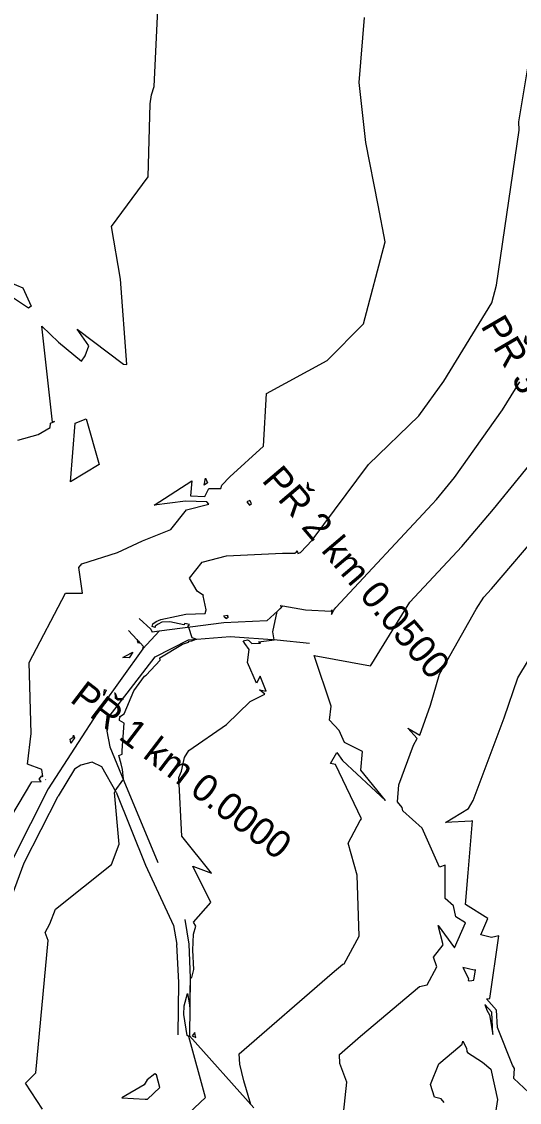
# Model space of a CAD drawing. Extents: x -549394 to -546608, y -1037055 to -1033629.
# Drawn here: x -547595.6 to -547431.1, y -1035265.1 to -1034908.3 of the extents above; entities that cross this region are included whole.
import ezdxf

# ---------------------------------------------------------------- set-up
doc = ezdxf.new("R2010")
doc.units = 0
for name, color, linetype in [('hlavni_vrst', 7, 'Continuous'), ('hrana_L', 7, 'Continuous'), ('norm_vrst', 7, 'Continuous'), ('x_popis_pricne_rezy_C14', 7, 'Continuous')]:
    doc.layers.add(name, color=color, linetype=linetype)

msp = doc.modelspace()

# ---------------------------------------------------------------- linework, layer by layer
at = {"layer": 'hlavni_vrst'}
for p, q in [((-547439.63, -1035069.29), (-547423.11, -1035049.09)), ((-547450.13, -1035081.66), (-547439.63, -1035069.29)), ((-547467.32, -1035100.01), (-547450.13, -1035081.66)), ((-547479.83, -1035120.29), (-547467.32, -1035100.01)), ((-547498.94, -1035117.55), (-547498.94, -1035117.55)), ((-547498.94, -1035117.55), (-547498.94, -1035117.55)), ((-547498.94, -1035117.55), (-547498.94, -1035117.55)), ((-547498.94, -1035117.55), (-547480.25, -1035121.02)), ((-547498.94, -1035117.55), (-547498.94, -1035117.55)), ((-547493.26, -1035134.32), (-547498.94, -1035117.55)), ((-547498.94, -1035117.55), (-547498.94, -1035117.55)), ((-547498.94, -1035117.55), (-547498.94, -1035117.55)), ((-547498.94, -1035117.55), (-547498.94, -1035117.55)), ((-547480.25, -1035121.02), (-547479.83, -1035120.29)), ((-547493.87, -1035138.92), (-547493.26, -1035134.32)), ((-547490.66, -1035142.33), (-547493.87, -1035138.92)), ((-547488.93, -1035146.33), (-547490.66, -1035142.33)), ((-547482.97, -1035149.28), (-547488.93, -1035146.33)), ((-547493.51, -1035153.28), (-547491.47, -1035149.64)), ((-547491.47, -1035149.64), (-547489.56, -1035152.3)), ((-547483.54, -1035155.44), (-547482.97, -1035149.28)), ((-547491.88, -1035153.58), (-547493.51, -1035153.28)), ((-547483.29, -1035171.5), (-547491.88, -1035153.58)), ((-547489.56, -1035152.3), (-547475.31, -1035165.43)), ((-547475.31, -1035165.43), (-547483.54, -1035155.44)), ((-547487.72, -1035179.56), (-547483.7, -1035172.06)), ((-547483.7, -1035172.06), (-547483.29, -1035171.5)), ((-547484.7, -1035190.12), (-547487.72, -1035179.56)), ((-547483.99, -1035210.2), (-547484.7, -1035190.12)), ((-547488.97, -1035219.38), (-547483.99, -1035210.2)), ((-547492.94, -1035222.45), (-547489.42, -1035219.48)), ((-547489.42, -1035219.48), (-547488.97, -1035219.38)), ((-547523.68, -1035249.07), (-547492.94, -1035222.45)), ((-547523.47, -1035252.45), (-547523.68, -1035249.07)), ((-547522.11, -1035257.98), (-547523.47, -1035252.45)), ((-547519.79, -1035265.79), (-547522.11, -1035257.98))]:
    msp.add_line(p, q, dxfattribs=at)
at = {"layer": 'hrana_L'}
for p, q in [((-547509.73, -1035101.72), (-547514.54, -1035106.1)), ((-547509.73, -1035101.72), (-547509.94, -1035101)), ((-547556.67, -1035105.35), (-547552.91, -1035108.87)), ((-547552.91, -1035108.87), (-547552.47, -1035109.91)), ((-547528.76, -1035106.82), (-547550.14, -1035109.56)), ((-547514.54, -1035106.1), (-547528.76, -1035106.82)), ((-547560.26, -1035109.29), (-547557.54, -1035112.36)), ((-547557.54, -1035112.36), (-547556.92, -1035113.1)), ((-547550.14, -1035109.56), (-547555.52, -1035115.44)), ((-547550.14, -1035109.56), (-547552.47, -1035109.91)), ((-547551.39, -1035118.06), (-547540.44, -1035112.37)), ((-547540.44, -1035112.37), (-547526.63, -1035111.28)), ((-547526.63, -1035111.28), (-547511.12, -1035112.47)), ((-547511.12, -1035112.47), (-547500.41, -1035113.54)), ((-547555.52, -1035115.44), (-547569.35, -1035134.71)), ((-547556.92, -1035113.1), (-547556.4, -1035113.41)), ((-547556.4, -1035113.41), (-547555.25, -1035114.57)), ((-547555.52, -1035115.44), (-547555.25, -1035114.57)), ((-547566.63, -1035137.73), (-547551.39, -1035118.06)), ((-547569.35, -1035134.71), (-547586.77, -1035161.66)), ((-547566.63, -1035137.73), (-547567.41, -1035142.61)), ((-547567.41, -1035142.61), (-547566.36, -1035147.78)), ((-547566.36, -1035147.78), (-547561.74, -1035159)), ((-547578.03, -1035155.14), (-547583.42, -1035164.02)), ((-547575.97, -1035153.82), (-547578.03, -1035155.14)), ((-547572.21, -1035152.78), (-547575.97, -1035153.82)), ((-547569.03, -1035154.36), (-547572.21, -1035152.78)), ((-547564.35, -1035162.73), (-547569.03, -1035154.36)), ((-547561.74, -1035159), (-547550.54, -1035185.88)), ((-547586.77, -1035161.66), (-547598.46, -1035184.75)), ((-547594.73, -1035186.07), (-547583.42, -1035164.02)), ((-547564.35, -1035162.73), (-547554.58, -1035186.78)), ((-547601.35, -1035203.97), (-547594.73, -1035186.07)), ((-547554.58, -1035186.78), (-547545.4, -1035206.76)), ((-547541.65, -1035204.75), (-547540.31, -1035212.84)), ((-547545.4, -1035206.76), (-547544.22, -1035212.97)), ((-547543.64, -1035225.54), (-547544.22, -1035212.97)), ((-547540.31, -1035212.84), (-547539.9, -1035223.97)), ((-547543.79, -1035242.77), (-547543.64, -1035225.54)), ((-547539.9, -1035223.97), (-547540.11, -1035243.13)), ((-547540.11, -1035243.13), (-547518.88, -1035266.9))]:
    msp.add_line(p, q, dxfattribs=at)
at = {"layer": 'norm_vrst'}
for p, q in [((-547551.79, -1034929.72), (-547550.44, -1034902.07)), ((-547484.09, -1034928.4), (-547482.29, -1034906.98)), ((-547431.35, -1034941.44), (-547426.48, -1034912.33)), ((-547552.66, -1034932.51), (-547551.79, -1034929.72)), ((-547481.84, -1034948.28), (-547484.09, -1034928.4)), ((-547553.04, -1034935.48), (-547552.66, -1034932.51)), ((-547553.79, -1034959.56), (-547553.04, -1034935.48)), ((-547431.24, -1034944.16), (-547431.35, -1034941.44)), ((-547438.69, -1034995.3), (-547431.24, -1034944.16)), ((-547477.76, -1034968.93), (-547481.84, -1034948.28)), ((-547565.89, -1034976.01), (-547553.79, -1034959.56)), ((-547475.43, -1034981.06), (-547477.76, -1034968.93)), ((-547562.89, -1034993.39), (-547565.89, -1034976.01)), ((-547482.58, -1035008.1), (-547475.43, -1034981.06)), ((-547593.26, -1035002.94), (-547617.79, -1034986.8)), ((-547617.79, -1034986.8), (-547595.13, -1034996.25)), ((-547560.84, -1035021.55), (-547562.89, -1034993.39)), ((-547595.13, -1034996.25), (-547592.37, -1035002.28)), ((-547440.2, -1035001.18), (-547438.69, -1034995.3)), ((-547456.12, -1035027.06), (-547440.2, -1035001.18)), ((-547592.37, -1035002.28), (-547593.26, -1035002.94)), ((-547588.88, -1035008.82), (-547583.39, -1035014.14)), ((-547585.36, -1035040.55), (-547588.88, -1035008.82)), ((-547494.58, -1035020.17), (-547482.58, -1035008.1)), ((-547573.36, -1035015.36), (-547577.22, -1035009.9)), ((-547577.22, -1035009.9), (-547561.9, -1035021.39)), ((-547583.39, -1035014.14), (-547575.79, -1035020.48)), ((-547574.57, -1035018.71), (-547573.36, -1035015.36)), ((-547575.79, -1035020.48), (-547574.57, -1035018.71)), ((-547561.9, -1035021.39), (-547560.84, -1035021.55)), ((-547514.67, -1035031.07), (-547494.58, -1035020.17)), ((-547464.29, -1035038.5), (-547456.12, -1035027.06)), ((-547436.64, -1035036.48), (-547430.97, -1035027.25)), ((-547515.69, -1035048.49), (-547514.67, -1035031.07)), ((-547452.59, -1035058.81), (-547436.64, -1035036.48)), ((-547586.09, -1035042.33), (-547585.98, -1035040.86)), ((-547585.98, -1035040.86), (-547584.68, -1035040.37)), ((-547584.68, -1035040.37), (-547585.36, -1035040.55)), ((-547579.44, -1035060.31), (-547577.91, -1035040.91)), ((-547577.91, -1035040.91), (-547574.2, -1035039.51)), ((-547574.2, -1035039.51), (-547569.97, -1035054.57)), ((-547480.94, -1035054.58), (-547464.29, -1035038.5)), ((-547596.78, -1035046.48), (-547590.08, -1035044.68)), ((-547590.08, -1035044.68), (-547586.09, -1035042.33)), ((-547526.74, -1035058.63), (-547515.69, -1035048.49)), ((-547569.97, -1035054.57), (-547579.44, -1035060.31)), ((-547499.6, -1035079.52), (-547480.94, -1035054.58)), ((-547535.26, -1035061.32), (-547534.84, -1035059.05)), ((-547534.84, -1035059.05), (-547534.1, -1035060.59)), ((-547529.36, -1035061.34), (-547526.74, -1035058.63)), ((-547458.52, -1035066.05), (-547452.59, -1035058.81)), ((-547551.78, -1035067.99), (-547539.33, -1035059.97)), ((-547539.33, -1035059.97), (-547539.8, -1035064.93)), ((-547534.1, -1035060.59), (-547535.26, -1035061.32)), ((-547535.01, -1035065.1), (-547533.68, -1035062.42)), ((-547533.68, -1035062.42), (-547529.79, -1035062.46)), ((-547529.79, -1035062.46), (-547529.36, -1035061.34)), ((-547539.8, -1035064.93), (-547535.01, -1035065.1)), ((-547459.89, -1035067.67), (-547458.52, -1035066.05)), ((-547541.44, -1035066.59), (-547551.78, -1035067.99)), ((-547546.28, -1035076.04), (-547541.11, -1035069.46)), ((-547534.39, -1035066.81), (-547541.44, -1035066.59)), ((-547541.11, -1035069.46), (-547533.73, -1035067.58)), ((-547533.73, -1035067.58), (-547534.39, -1035066.81)), ((-547520.21, -1035066.44), (-547521.2, -1035066.83)), ((-547521.2, -1035066.83), (-547520.26, -1035067.93)), ((-547520.26, -1035067.93), (-547519.62, -1035067.42)), ((-547519.62, -1035067.42), (-547520.21, -1035066.44)), ((-547491.77, -1035101.71), (-547459.89, -1035067.67)), ((-547440.38, -1035095.64), (-547420.74, -1035072.52)), ((-547555.56, -1035079.72), (-547546.28, -1035076.04)), ((-547563.91, -1035083.64), (-547555.56, -1035079.72)), ((-547503.4, -1035083.58), (-547499.6, -1035079.52)), ((-547575.71, -1035087.34), (-547563.91, -1035083.64)), ((-547527.84, -1035084.74), (-547509.37, -1035083.84)), ((-547509.37, -1035083.84), (-547505.24, -1035083.85)), ((-547505.24, -1035083.85), (-547504.71, -1035083.33)), ((-547504.71, -1035083.33), (-547504.53, -1035083.09)), ((-547504.53, -1035083.09), (-547504.35, -1035083.91)), ((-547504.35, -1035083.91), (-547503.4, -1035083.58)), ((-547576.61, -1035088.51), (-547575.71, -1035087.34)), ((-547540.04, -1035092.08), (-547535.88, -1035086.78)), ((-547535.88, -1035086.78), (-547527.84, -1035084.74)), ((-547575.48, -1035097), (-547576.61, -1035088.51)), ((-547537.54, -1035096.4), (-547540.04, -1035092.08)), ((-547593.1, -1035119.88), (-547581.07, -1035097.02)), ((-547581.07, -1035097.02), (-547575.48, -1035097)), ((-547535.49, -1035097.8), (-547537.54, -1035096.4)), ((-547535.61, -1035097.89), (-547535.49, -1035097.8)), ((-547534.57, -1035102.57), (-547535.61, -1035097.89)), ((-547445.35, -1035102.31), (-547442.88, -1035098.31)), ((-547442.88, -1035098.31), (-547440.38, -1035095.64)), ((-547511.17, -1035103.03), (-547509.75, -1035101.64)), ((-547509.75, -1035101.64), (-547509.24, -1035101.21)), ((-547509.24, -1035101.21), (-547501.78, -1035102.57)), ((-547492.36, -1035102.68), (-547491.77, -1035101.71)), ((-547549.61, -1035105.76), (-547544.42, -1035104.64)), ((-547544.42, -1035104.64), (-547541.25, -1035103.92)), ((-547541.25, -1035103.92), (-547534.92, -1035103.73)), ((-547534.92, -1035103.73), (-547534.57, -1035102.57)), ((-547528.79, -1035104.51), (-547527.52, -1035104.28)), ((-547528.43, -1035105.18), (-547528.79, -1035104.51)), ((-547528, -1035105.18), (-547528.43, -1035105.18)), ((-547527.97, -1035105.44), (-547528, -1035105.18)), ((-547527.34, -1035105.07), (-547527.97, -1035105.44)), ((-547527.52, -1035104.28), (-547527.55, -1035104.73)), ((-547527.55, -1035104.73), (-547527.34, -1035105.07)), ((-547512.55, -1035109.82), (-547511.17, -1035103.03)), ((-547501.78, -1035102.57), (-547493.31, -1035102.92)), ((-547493.31, -1035102.92), (-547493.12, -1035102.53)), ((-547493.12, -1035102.53), (-547493.18, -1035104.1)), ((-547493.18, -1035104.1), (-547492.36, -1035102.68)), ((-547457.52, -1035123.77), (-547445.35, -1035102.31)), ((-547552.39, -1035108.05), (-547552.18, -1035107.09)), ((-547551.47, -1035108.32), (-547552.39, -1035108.05)), ((-547552.18, -1035107.09), (-547551.08, -1035106.42)), ((-547551.4, -1035107.96), (-547551.47, -1035108.32)), ((-547550.47, -1035107.26), (-547551.4, -1035107.96)), ((-547551.08, -1035106.42), (-547549.61, -1035105.76)), ((-547549.23, -1035106.57), (-547550.47, -1035107.26)), ((-547546.54, -1035106.51), (-547549.23, -1035106.57)), ((-547541.97, -1035107.51), (-547546.54, -1035106.51)), ((-547541.62, -1035107.03), (-547541.97, -1035107.51)), ((-547540.08, -1035107.36), (-547541.62, -1035107.03)), ((-547540.65, -1035107.76), (-547540.08, -1035107.36)), ((-547540.35, -1035108.31), (-547540.65, -1035107.76)), ((-547539.18, -1035111.77), (-547540.35, -1035108.31)), ((-547540.19, -1035112.88), (-547539.36, -1035112.71)), ((-547539.36, -1035112.71), (-547537.9, -1035112.17)), ((-547537.9, -1035112.17), (-547539.18, -1035111.77)), ((-547522.36, -1035112.78), (-547520.92, -1035112.39)), ((-547520.92, -1035112.39), (-547520.45, -1035112.67)), ((-547520.45, -1035112.67), (-547519.48, -1035113.67)), ((-547517.3, -1035113.1), (-547512.88, -1035112.5)), ((-547513.13, -1035112.4), (-547512.17, -1035112.39)), ((-547512.88, -1035112.5), (-547513.13, -1035112.4)), ((-547512.17, -1035112.39), (-547512.55, -1035109.82)), ((-547557.29, -1035112.96), (-547557.19, -1035112.78)), ((-547556.91, -1035113.61), (-547557.29, -1035112.96)), ((-547557.19, -1035112.78), (-547556.86, -1035112.88)), ((-547556.76, -1035113.2), (-547556.91, -1035113.61)), ((-547556.86, -1035112.88), (-547556.76, -1035113.2)), ((-547549.9, -1035118.39), (-547542.36, -1035113.9)), ((-547542.36, -1035113.9), (-547540.37, -1035113.22)), ((-547540.37, -1035113.22), (-547540.19, -1035112.88)), ((-547521.86, -1035113.6), (-547522.36, -1035112.78)), ((-547520.33, -1035115.59), (-547521.86, -1035113.6)), ((-547520.94, -1035119.91), (-547520.33, -1035115.59)), ((-547519.48, -1035113.67), (-547516.67, -1035113.57)), ((-547516.67, -1035113.57), (-547517.3, -1035113.1)), ((-547431.58, -1035124.92), (-547424.58, -1035113.3)), ((-547592.42, -1035143.29), (-547593.1, -1035119.88)), ((-547562.08, -1035118.24), (-547561.09, -1035117.72)), ((-547560.06, -1035118.37), (-547562.08, -1035118.24)), ((-547561.09, -1035117.72), (-547558.85, -1035116.54)), ((-547558.85, -1035116.54), (-547560.06, -1035118.37)), ((-547554.44, -1035124.11), (-547549.77, -1035119.14)), ((-547549.77, -1035119.14), (-547549.9, -1035118.39)), ((-547517.94, -1035126.69), (-547520.94, -1035119.91)), ((-547558.45, -1035129.26), (-547554.97, -1035124.44)), ((-547554.97, -1035124.44), (-547554.44, -1035124.11)), ((-547516.76, -1035124.47), (-547517.94, -1035126.69)), ((-547514.77, -1035129.37), (-547516.76, -1035124.47)), ((-547460.51, -1035134.02), (-547457.52, -1035123.77)), ((-547436.15, -1035138.18), (-547431.58, -1035124.92)), ((-547568.37, -1035130.8), (-547568.19, -1035128.87)), ((-547567.58, -1035129.02), (-547568.37, -1035130.8)), ((-547568.19, -1035128.87), (-547567.58, -1035129.02)), ((-547561.65, -1035136.86), (-547558.45, -1035129.26)), ((-547520.05, -1035132.83), (-547515.15, -1035130.32)), ((-547515.15, -1035130.32), (-547516.97, -1035128.88)), ((-547516.97, -1035128.88), (-547514.77, -1035129.37)), ((-547527.89, -1035140.38), (-547520.05, -1035132.83)), ((-547464.01, -1035143.87), (-547460.51, -1035134.02)), ((-547563.23, -1035137.82), (-547561.65, -1035136.86)), ((-547563.02, -1035137.96), (-547563.23, -1035137.82)), ((-547563.23, -1035139.05), (-547563.22, -1035138.41)), ((-547561.64, -1035139.98), (-547563.23, -1035139.05)), ((-547563.22, -1035138.41), (-547563.02, -1035137.96)), ((-547562.37, -1035148.95), (-547561.64, -1035139.98)), ((-547540.33, -1035148.97), (-547527.89, -1035140.38)), ((-547446.37, -1035165.49), (-547436.15, -1035138.18)), ((-547593.6, -1035153.5), (-547592.42, -1035143.29)), ((-547579.54, -1035145.23), (-547578.47, -1035144.58)), ((-547578.12, -1035144.81), (-547579.31, -1035146.56)), ((-547578.47, -1035144.58), (-547578.46, -1035143.93)), ((-547578.46, -1035143.93), (-547578.12, -1035144.81)), ((-547464.91, -1035144.94), (-547467.94, -1035141.53)), ((-547467.94, -1035141.53), (-547464.01, -1035143.87)), ((-547579.31, -1035146.56), (-547579.54, -1035145.23)), ((-547470.9, -1035160.29), (-547466.11, -1035147.23)), ((-547466.11, -1035147.23), (-547464.91, -1035144.94)), ((-547563.44, -1035150.64), (-547562.32, -1035150.12)), ((-547562.68, -1035153.31), (-547563.44, -1035150.64)), ((-547562.32, -1035150.12), (-547562.37, -1035148.95)), ((-547542.76, -1035155.82), (-547541.7, -1035151.24)), ((-547541.7, -1035151.24), (-547540.33, -1035148.97)), ((-547588.91, -1035155.18), (-547593.6, -1035153.5)), ((-547588.5, -1035157.53), (-547588.91, -1035155.18)), ((-547562.19, -1035155.28), (-547562.68, -1035153.31)), ((-547561.92, -1035158.36), (-547562.19, -1035155.28)), ((-547589.75, -1035158.44), (-547588.88, -1035157.29)), ((-547589.1, -1035159.23), (-547589.75, -1035158.44)), ((-547588.88, -1035157.29), (-547588.86, -1035157.27)), ((-547588.86, -1035157.27), (-547588.5, -1035157.53)), ((-547587.69, -1035158.67), (-547587.56, -1035158.52)), ((-547587.52, -1035158.57), (-547587.69, -1035158.67)), ((-547587.56, -1035158.52), (-547587.5, -1035158.56)), ((-547587.5, -1035158.56), (-547587.52, -1035158.57)), ((-547564.6, -1035162.29), (-547562.12, -1035158.76)), ((-547562.12, -1035158.76), (-547561.93, -1035158.53)), ((-547561.93, -1035158.53), (-547561.92, -1035158.36)), ((-547543.6, -1035157.83), (-547542.76, -1035155.82)), ((-547542.66, -1035177.19), (-547543.6, -1035157.83)), ((-547601.22, -1035174.47), (-547592.16, -1035159.27)), ((-547592.16, -1035159.27), (-547589.1, -1035159.23)), ((-547564.89, -1035162.77), (-547564.66, -1035162.56)), ((-547564.66, -1035162.56), (-547564.6, -1035162.29)), ((-547471.41, -1035165.85), (-547470.9, -1035160.29)), ((-547563.32, -1035179.88), (-547564.89, -1035162.77)), ((-547469.79, -1035167.81), (-547471.41, -1035165.85)), ((-547447.91, -1035168.13), (-547446.37, -1035165.49)), ((-547469.59, -1035168.84), (-547469.79, -1035167.81)), ((-547463.25, -1035174.61), (-547469.59, -1035168.84)), ((-547455.5, -1035172.67), (-547447.91, -1035168.13)), ((-547447, -1035172.23), (-547455.5, -1035172.67)), ((-547455.5, -1035172.67), (-547455.5, -1035172.67)), ((-547455.5, -1035172.67), (-547455.5, -1035172.67)), ((-547455.5, -1035172.67), (-547455.5, -1035172.67)), ((-547455.5, -1035172.67), (-547455.5, -1035172.67)), ((-547455.5, -1035172.67), (-547455.5, -1035172.67)), ((-547448.06, -1035189.29), (-547446.65, -1035172.21)), ((-547446.65, -1035172.21), (-547447, -1035172.23)), ((-547457.56, -1035187.43), (-547463.25, -1035174.61)), ((-547565.84, -1035186.58), (-547563.32, -1035179.88)), ((-547532.84, -1035189.49), (-547542.66, -1035177.19)), ((-547584.35, -1035201.32), (-547565.84, -1035186.58)), ((-547533.05, -1035199.15), (-547538.95, -1035187.12)), ((-547538.95, -1035187.12), (-547532.84, -1035189.49)), ((-547455.58, -1035186.85), (-547457.56, -1035187.43)), ((-547455.6, -1035197.85), (-547455.58, -1035186.85)), ((-547448.87, -1035199.84), (-547448.06, -1035189.29)), ((-547452.87, -1035200.27), (-547455.6, -1035197.85)), ((-547586.27, -1035206.2), (-547584.35, -1035201.32)), ((-547538.82, -1035205.63), (-547533.05, -1035199.15)), ((-547452.09, -1035203.85), (-547452.87, -1035200.27)), ((-547441.49, -1035204.44), (-547448.87, -1035199.84)), ((-547448.94, -1035205.81), (-547452.09, -1035203.85)), ((-547443.87, -1035209.85), (-547441.49, -1035204.44)), ((-547587.78, -1035209.07), (-547586.27, -1035206.2)), ((-547586.75, -1035211.7), (-547587.78, -1035209.07)), ((-547537.95, -1035206.9), (-547538.82, -1035205.63)), ((-547538.8, -1035209.61), (-547537.95, -1035206.9)), ((-547457.93, -1035206.68), (-547452.59, -1035214.12)), ((-547456.28, -1035213.14), (-547457.93, -1035206.68)), ((-547452.59, -1035214.12), (-547448.94, -1035205.81)), ((-547590.83, -1035255.39), (-547586.75, -1035211.7)), ((-547538.96, -1035214.88), (-547538.8, -1035209.61)), ((-547440.34, -1035210.71), (-547443.87, -1035209.85)), ((-547440.86, -1035230.85), (-547437.93, -1035210.18)), ((-547437.93, -1035210.18), (-547440.34, -1035210.71)), ((-547538.67, -1035221.2), (-547538.96, -1035214.88)), ((-547459.51, -1035217.16), (-547456.28, -1035213.14)), ((-547458.44, -1035220.39), (-547459.51, -1035217.16)), ((-547539.33, -1035223.84), (-547538.67, -1035221.2)), ((-547461.63, -1035226.27), (-547458.44, -1035220.39)), ((-547449.82, -1035220.54), (-547447.89, -1035224.24)), ((-547446.06, -1035221.45), (-547449.82, -1035220.54)), ((-547446.15, -1035224.81), (-547445.66, -1035221.36)), ((-547445.66, -1035221.36), (-547446.06, -1035221.45)), ((-547540.01, -1035233.55), (-547539.76, -1035224.13)), ((-547539.76, -1035224.13), (-547539.33, -1035223.84)), ((-547483.65, -1035243.3), (-547464.16, -1035226.84)), ((-547464.16, -1035226.84), (-547461.63, -1035226.27)), ((-547447.89, -1035224.24), (-547448.08, -1035224.9)), ((-547448.08, -1035224.9), (-547447.53, -1035224.94)), ((-547447.53, -1035224.94), (-547446.15, -1035224.81)), ((-547541.85, -1035233.2), (-547540.73, -1035229.23)), ((-547540.73, -1035229.23), (-547540.01, -1035233.55)), ((-547542, -1035236.14), (-547541.85, -1035233.2)), ((-547442.5, -1035232.79), (-547441.86, -1035234.63)), ((-547440.24, -1035235.34), (-547442.5, -1035232.79)), ((-547442.02, -1035230.96), (-547440.86, -1035230.85)), ((-547438.69, -1035234.71), (-547442.02, -1035230.96)), ((-547540.85, -1035243.06), (-547542, -1035236.14)), ((-547441.86, -1035234.63), (-547440.97, -1035236.26)), ((-547440.97, -1035236.26), (-547439.85, -1035242.68)), ((-547439.85, -1035242.68), (-547440.24, -1035235.34)), ((-547438.39, -1035240.39), (-547438.69, -1035234.71)), ((-547433.36, -1035252.86), (-547438.39, -1035240.39)), ((-547540.32, -1035243.38), (-547540.85, -1035243.06)), ((-547534.75, -1035263.47), (-547540.32, -1035243.38)), ((-547538.33, -1035242.06), (-547539.23, -1035243.18)), ((-547539.23, -1035243.18), (-547538, -1035243.67)), ((-547538.19, -1035242.73), (-547538.33, -1035242.06)), ((-547538.09, -1035243.35), (-547538.19, -1035242.73)), ((-547538, -1035243.67), (-547538.09, -1035243.35)), ((-547490.56, -1035249.29), (-547483.65, -1035243.3)), ((-547457.75, -1035252.36), (-547452.88, -1035248.29)), ((-547452.88, -1035248.29), (-547450.03, -1035245.86)), ((-547450.03, -1035245.86), (-547449.83, -1035244.96)), ((-547449.83, -1035244.96), (-547448.63, -1035247.18)), ((-547448.63, -1035247.18), (-547448.43, -1035248.32)), ((-547448.43, -1035248.32), (-547448.22, -1035248.63)), ((-547490.38, -1035252.33), (-547490.56, -1035249.29)), ((-547448.22, -1035248.63), (-547443.34, -1035251.83)), ((-547443.34, -1035251.83), (-547440.51, -1035254.12)), ((-547594.25, -1035258.73), (-547590.83, -1035255.39)), ((-547488.13, -1035258.5), (-547490.38, -1035252.33)), ((-547460.47, -1035259.23), (-547457.75, -1035252.36)), ((-547440.51, -1035254.12), (-547438.37, -1035264.15)), ((-547432.7, -1035253.95), (-547433.36, -1035252.86)), ((-547432.95, -1035257.28), (-547432.7, -1035253.95)), ((-547588.62, -1035267.38), (-547594.25, -1035258.73)), ((-547554.08, -1035257.72), (-547555.06, -1035259.28)), ((-547551.59, -1035255.7), (-547554.08, -1035257.72)), ((-547551.02, -1035256.06), (-547551.59, -1035255.7)), ((-547549.87, -1035260.21), (-547551.02, -1035256.06)), ((-547489.23, -1035268.75), (-547488.13, -1035258.5)), ((-547421.19, -1035268.25), (-547432.95, -1035257.28)), ((-547555.06, -1035259.28), (-547562.42, -1035263.57)), ((-547553.94, -1035264.07), (-547549.87, -1035260.21)), ((-547459.13, -1035263.43), (-547460.47, -1035259.23)), ((-547562.42, -1035263.57), (-547554.76, -1035264.08)), ((-547554.76, -1035264.08), (-547553.94, -1035264.07)), ((-547540.26, -1035268.7), (-547534.75, -1035263.47)), ((-547456.94, -1035263.99), (-547459.13, -1035263.43)), ((-547455.97, -1035265.15), (-547456.94, -1035263.99)), ((-547438.37, -1035264.15), (-547439.38, -1035270.67))]:
    msp.add_line(p, q, dxfattribs=at)

# ---------------------------------------------------------------- texts
at = {"layer": 'x_popis_pricne_rezy_C14'}
for s, rotation, p in [('PŘ 3 km 0.1000', 300.1864, (-547444.08, -1035008.78)), ('PŘ 2 km 0.0500', 310.3541, (-547516.49, -1035059.88)), ('PŘ 1 km 0.0000', 322.6009, (-547579.94, -1035132.61))]:
    msp.add_text(s, height=9.0627, rotation=rotation, dxfattribs=at).set_placement(p)

doc.saveas('drawing.dxf')
